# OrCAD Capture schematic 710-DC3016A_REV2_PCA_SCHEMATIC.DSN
size Custom; company: ANALOG DEVICES; note: DEMO BOARD BILL OF MATERIALS; note: 2A BUCK-BOOST POWER uMODULE REGULATOR
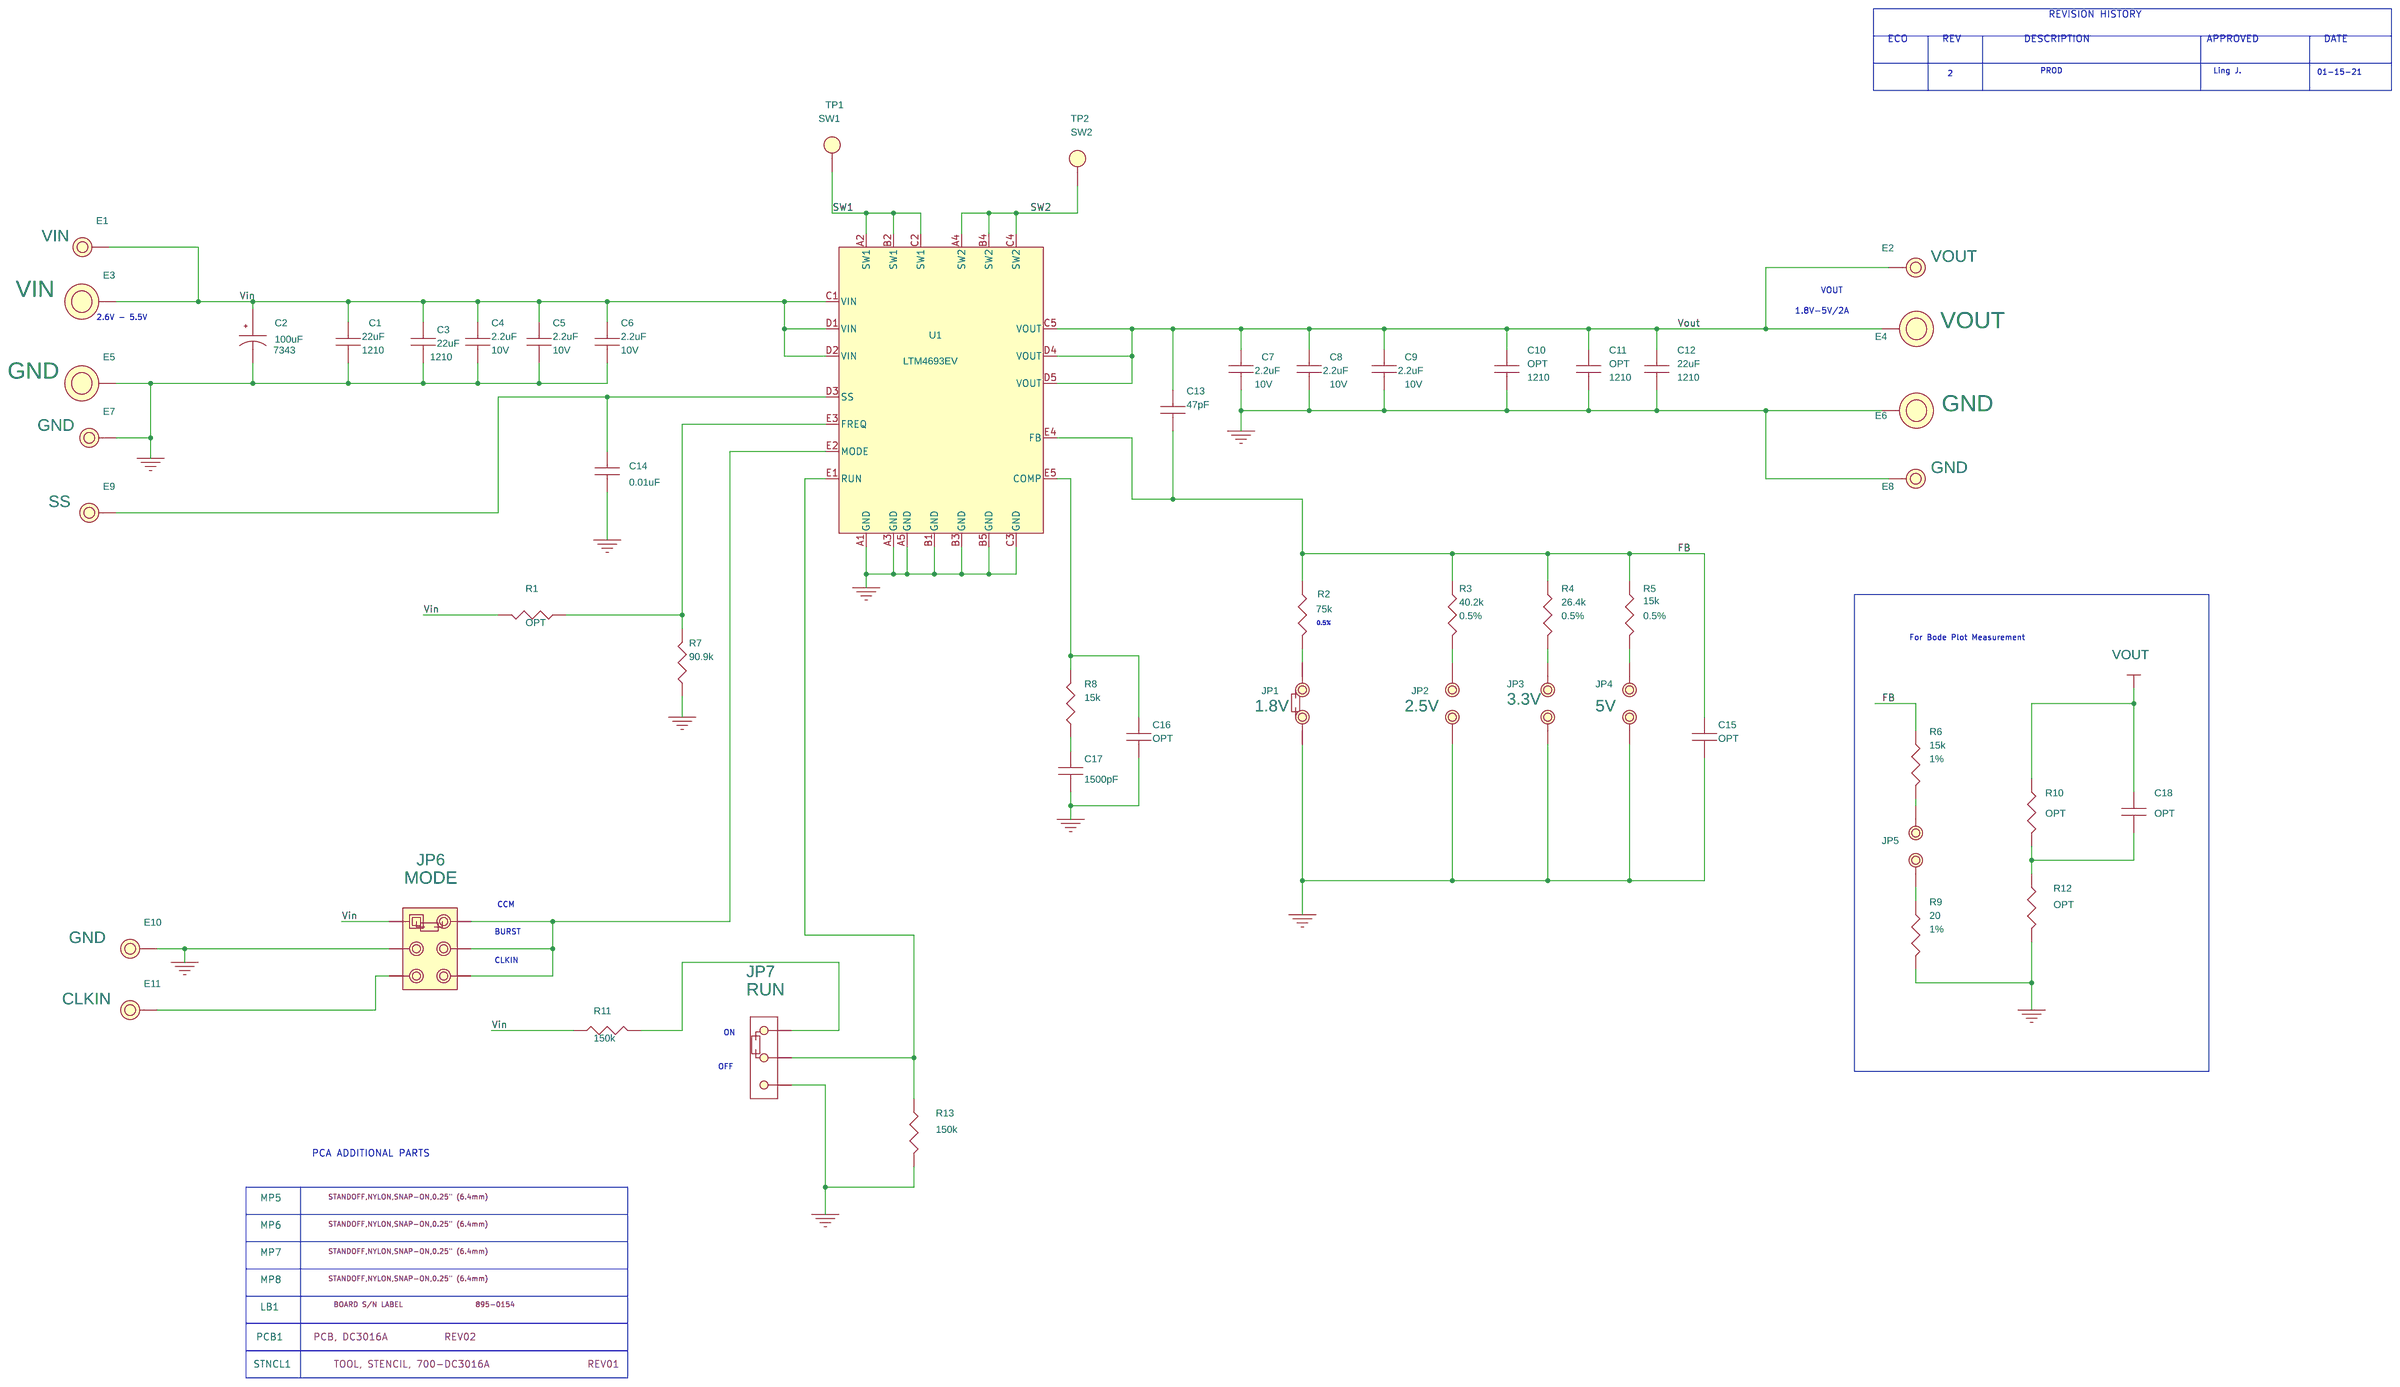
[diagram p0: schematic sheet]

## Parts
C1  22uF  [CC1210N]
C2  100uF  [CAPMP7343N]
C3  22uF  [CC1210N]
C4  2.2uF  [CC0603N]
C5  2.2uF  [CC0603N]
C6  2.2uF  [CC0603N]
C7  2.2uF  [CC0603N]
C8  2.2uF  [CC0603N]
C9  2.2uF  [CC0603N]
C10  OPT  [CC1210N]
C11  OPT  [CC1210N]
C12  22uF  [CC1210N]
C13  47pF  [CC0603N]
C14  0.01uF  [CC0603N]
C15  OPT  [CC0603N]
C16  OPT  [CC0603N]
C17  1500pF  [CC0603N]
C18  OPT  [CC0603N]
E1  TEST POINT  [MILLMAX2501]
E2  TEST POINT  [MILLMAX2501]
E3  BANANA JACK  [KEY-575-4]
E4  BANANA JACK  [KEY-575-4]
E5  BANANA JACK  [KEY-575-4]
E6  BANANA JACK  [KEY-575-4]
E7  TEST POINT  [MILLMAX2501]
E8  TEST POINT  [MILLMAX2501]
E9  TEST POINT  [MILLMAX2501]
E10  TEST POINT  [MILLMAX2501]
E11  TEST POINT  [MILLMAX2501]
JP1  HDR  [HD1X2-079]
JP2  HDR  [HD1X2-079]
JP3  HDR  [HD1X2-079]
JP4  HDR  [HD1X2-079]
JP5  HDR  [HD1X2-079]
JP6  HDR  [HD2X3-079]
JP7  HDR  [JP3X1/079]
LB1  LABEL  [895-0154_REV01]
MP5  STANDOFF  [MTG-8831]
MP6  STANDOFF  [MTG-8831]
MP7  STANDOFF  [MTG-8831]
MP8  STANDOFF  [MTG-8831]
PCB1  PCB, DC3016A
R1  OPT  [CR0603N]
R2  75k  [CR0603N]
R3  40.2k  [CR0603N]
R4  26.4k  [CR0603N]
R5  15k  [CR0603N]
R6  15k  [CR0603N]
R7  90.9k  [CR0603N]
R8  15k  [CR0603N]
R9  20  [CR0603N]
R10  OPT  [CR0603N]
R11  150k  [CR0603N]
R12  OPT  [CR0603N]
R13  150k  [CR0603N]
STNCL1  TOOL, STENCIL, 700-DC3016A
TP1  TEST PAD  [PADSTYLE1]
TP2  TEST PAD  [PADSTYLE1]
U1  LTM4693EV  [LTM4693EV]
XJP1  SHUNT  [SAMTEC-SHUNT-079]
XJP2  SHUNT  [SAMTEC-SHUNT-079]
XJP3  SHUNT  [SAMTEC-SHUNT-079]

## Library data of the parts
C1 C3 C12 = CAP: CAP.,22uF,X5R,25V,20%,1210; CLASS: DISCRETE; Dielectric Type: X5R; FPLIST: CC1210N,CC1210L,CC1210M; Inventory Qty: 6478; Manufacturer: AVX; Manufacturer PN: 12103D226MAT2A; PART_NUMBER: 150-3266; Package Size: 1210; Rated Voltage: 25V; Tolerance: 20%
C2 = CAP_P: CAP.,100uF,TANT. POSCAP,20V,20%,7343,55mOHMS, TQC, NO SUBS. ALLOWED; CLASS: DISCRETE; Dielectric Type: TANT. POSCAP; FPLIST: CAPMP7343N,CAPMP7343L,CAPMP7343M; Inventory Qty: 3536; Manufacturer: PANASONIC; Manufacturer PN: 20TQC100MYF; PART_NUMBER: 150-3320; Package Size: 7343; Rated Voltage: 20V; Tolerance: 20%
C4-C9 = CAP: CAP.,2.2uF,X7R,10V,10%,0603; CLASS: DISCRETE; Dielectric Type: X7R; FPLIST: CC0603N,CC0603L,CC0603M; Inventory Qty: 13671; Manufacturer: MURATA; Manufacturer PN: GRM188R71A225KE15D; PART_NUMBER: 150-2083; Package Size: 0603; Rated Voltage: 10V; Tolerance: 10%
C10 C11 = CAP: CAP., OPTION, 1210; CLASS: DISCRETE; FPLIST: CC1210N,CC1210L,CC1210M; PART_NUMBER: 150-3035; Package Size: 1210; Package Type: SMD
C13 = CAP: CAP.,47pF,X7R,50V,10%,0603; CLASS: DISCRETE; Dielectric Type: X7R; FPLIST: CC0603N,CC0603L,CC0603M; Inventory Qty: 8360; Manufacturer: AVX; Manufacturer PN: 06035C470KAT2A; PART_NUMBER: 150-2319; Package Size: 0603; Rated Voltage: 50V; Tolerance: 10%
C14 = CAP: CAP.,0.01uF,X7R,50V,10%,0603; CLASS: DISCRETE; Dielectric Type: X7R; FPLIST: CC0603N,CC0603L,CC0603M; Inventory Qty: 28483; Manufacturer: AVX; Manufacturer PN: 06035C103KAT2A; PART_NUMBER: 150-0002; Package Size: 0603; Rated Voltage: 50V; Tolerance: 10%
C15 = CAP: CAP., OPTION, 0603; CLASS: DISCRETE; FPLIST: CC0603N,CC0603L,CC0603M; PART_NUMBER: 150-3038; Package Size: 0603; Package Type: SMD; UserField01: OPTION
C16 C18 = CAP: CAP., OPTION, 0603; CLASS: DISCRETE; FPLIST: CC0603N,CC0603L,CC0603M; PART_NUMBER: 150-3038; Package Size: 0603; Package Type: SMD
C17 = CAP: CAP.,1500pF,X7R,50V,10%,0603; CLASS: DISCRETE; Dielectric Type: X7R; FPLIST: CC0603N,CC0603L,CC0603M; Inventory Qty: 16000; Manufacturer: AVX; Manufacturer PN: 06035C152KAT2A; PART_NUMBER: 150-0190; Package Size: 0603; Rated Voltage: 50V; Tolerance: 10%
E1 = TESTPOINT_.219_MILL-MAX_2501: TEST POINT,TURRET,0.094" MTG. HOLE,PCB 0.062" THK; CLASS: IO; Inventory Qty: 823526; Manufacturer: MILL-MAX; Manufacturer PN: 2501-2-00-80-00-00-07-0; PART_FIELD_01: VIN; PART_NUMBER: 260-0003
E2 = TESTPOINT_.219_MILL-MAX_2501: TEST POINT,TURRET,0.094" MTG. HOLE,PCB 0.062" THK; CLASS: IO; Inventory Qty: 823526; Manufacturer: MILL-MAX; Manufacturer PN: 2501-2-00-80-00-00-07-0; PART_FIELD_01: VOUT; PART_NUMBER: 260-0003
E3 = BANANA_KEYSTONE-575-4: CONN.,BANANA JACK,FEMALE,THT,NON-INSULATED,SWAGE,0.218"; CLASS: IO; Inventory Qty: 203061; Manufacturer: KEYSTONE; Manufacturer PN: 575-4; PART_FIELD_01: VIN; PART_NUMBER: 250-0428
E4 = BANANA_KEYSTONE-575-4: CONN.,BANANA JACK,FEMALE,THT,NON-INSULATED,SWAGE,0.218"; CLASS: IO; Inventory Qty: 203061; Manufacturer: KEYSTONE; Manufacturer PN: 575-4; PART_FIELD_01: VOUT; PART_NUMBER: 250-0428
E5 E6 = BANANA_KEYSTONE-575-4: CONN.,BANANA JACK,FEMALE,THT,NON-INSULATED,SWAGE,0.218"; CLASS: IO; Inventory Qty: 203061; Manufacturer: KEYSTONE; Manufacturer PN: 575-4; PART_FIELD_01: GND; PART_NUMBER: 250-0428
E7 E8 E10 = TESTPOINT_.219_MILL-MAX_2501: TEST POINT,TURRET,0.094" MTG. HOLE,PCB 0.062" THK; CLASS: IO; Inventory Qty: 823526; Manufacturer: MILL-MAX; Manufacturer PN: 2501-2-00-80-00-00-07-0; PART_FIELD_01: GND; PART_NUMBER: 260-0003
E9 = TESTPOINT_.219_MILL-MAX_2501: TEST POINT,TURRET,0.094" MTG. HOLE,PCB 0.062" THK; CLASS: IO; Inventory Qty: 823526; Manufacturer: MILL-MAX; Manufacturer PN: 2501-2-00-80-00-00-07-0; PART_FIELD_01: SS; PART_NUMBER: 260-0003
E11 = TESTPOINT_.219_MILL-MAX_2501: TEST POINT,TURRET,0.094" MTG. HOLE,PCB 0.062" THK; CLASS: IO; Inventory Qty: 823526; Manufacturer: MILL-MAX; Manufacturer PN: 2501-2-00-80-00-00-07-0; PART_FIELD_01: CLKIN; PART_NUMBER: 260-0003
JP1 = HDR1X2_ALT1_3: CONN.,HDR,MALE,1x2,2mm,VERT,ST,THT; 9th Part Field: 1.8V; CLASS: IO; Inventory Qty: 72596; Manufacturer: SULLINS CONNECTOR SOLUTIONS; Manufacturer PN: NRPN021PAEN-RC; PART_NUMBER: 250-0449
JP2 = HDR1X2_ALT1_2: CONN.,HDR,MALE,1x2,2mm,VERT,ST,THT; 9th Part Field: 2.5V; CLASS: IO; Inventory Qty: 72596; Manufacturer: SULLINS CONNECTOR SOLUTIONS; Manufacturer PN: NRPN021PAEN-RC; PART_NUMBER: 250-0449
JP3 = HDR1X2_ALT1_1: CONN.,HDR,MALE,1x2,2mm,VERT,ST,THT; 9th Part Field: 3.3V; CLASS: IO; Inventory Qty: 72596; Manufacturer: SULLINS CONNECTOR SOLUTIONS; Manufacturer PN: NRPN021PAEN-RC; PART_NUMBER: 250-0449
JP4 = HDR1X2_ALT1: CONN.,HDR,MALE,1x2,2mm,VERT,ST,THT; 9th Part Field: 5V; CLASS: IO; Inventory Qty: 72596; Manufacturer: SULLINS CONNECTOR SOLUTIONS; Manufacturer PN: NRPN021PAEN-RC; PART_NUMBER: 250-0449
JP5 = HDR1X2_ALT1_4: CONN.,HDR,MALE,1x2,2mm,VERT,ST,THT; 9th Part Field: 5V; CLASS: IO; Inventory Qty: 72596; Manufacturer: SULLINS CONNECTOR SOLUTIONS; Manufacturer PN: NRPN021PAEN-RC; PART_NUMBER: 250-0449
JP6 = HDR2X3_ALT1: CONN.,HDR,MALE,2x3,2mm,VERT,ST,THT; 9th Part Field: MODE; CLASS: IO; Inventory Qty: 28346; Manufacturer: SULLINS CONNECTOR SOLUTIONS; Manufacturer PN: NRPN032PAEN-RC; PART_NUMBER: 250-0430
JP7 = 1X3: CONN.,HDR,MALE,1x3,2mm,VERT,ST,THT,NO SUBS. ALLOWED; CLASS: IO; FPLIST: JP3X1/079,HD1X3-079; Inventory Qty: 7904; Manufacturer: SAMTEC; Manufacturer PN: TMM-103-02-L-S; PART_FIELD_01: RUN; PART_NUMBER: 250-0638
LB1 = BLANK_LABEL: LABEL SPEC, DEMO BOARD SERIAL NUMBER; Inventory Qty: 0; Manufacturer: BRADY; Manufacturer PN: THT-96-717-10; PART_FIELD_01: BOARD S/N LABEL; PART_NUMBER: 895-0154
MP5-MP8 = BLANK_MECHANICAL_PART: STANDOFF,NYLON,SNAP-ON,0.25" (6.4mm); CLASS: DISCRETE; Inventory Qty: 227624; Manufacturer: KEYSTONE; Manufacturer PN: 8831; PART_NUMBER: 763-0006
PCB1 = BLANK_PCB_PART: BOM Notes: REV02; CLASS: DISCRETE; Inventory Qty: 0; Manufacturer: MAO BANG; Manufacturer PN: 600-DC3016A; PART_NUMBER: 600-DC3016A
R1 R10 R12 = RES: RES., OPTION, 0603; CLASS: DISCRETE; FPLIST: CR0603N,CR0603L,CR0603M; PART_NUMBER: 100-2374; Package Size: 0603
R2 = RES: RES.,75k OHMS,0.5%,1/5W,0603; CLASS: DISCRETE; FPLIST: CR0603N,CR0603L,CR0603M; Inventory Qty: 20320; Manufacturer: PANASONIC; Manufacturer PN: ERJ-PB3D7502V; PART_NUMBER: TMP-7179; Package Size: 0603
R3 = RES: RES.,40.2k OHMS,0.5%,1/16W,0603,METAL THIN FILM; CLASS: DISCRETE; FPLIST: CR0603N,CR0603L,CR0603M; Inventory Qty: 9482; Manufacturer: Susumu; Manufacturer PN: RR0816P-4022-D-59C; PART_NUMBER: 100-2124; Package Size: 0603; Rated Power: 1/16W; Temperature Coefficient: +/-25ppm; Tolerance: 0.5%
R4 = RES: RES.,26.4K OHMS,0.5%,1/10W,0603,THIN FILM; CLASS: DISCRETE; FPLIST: CR0603N,CR0603L,CR0603M; Inventory Qty: 10000; Manufacturer: YAGEO; Manufacturer PN: RT0603DRE0726K4L; PART_NUMBER: 100-1564; Package Size: 0603; Rated Power: 1/10W; Temperature Coefficient: +/-50PPM; Tolerance: 0.5%
R5 = RES: RES.,15k OHMS,0.5%,1/10W,0603; CLASS: DISCRETE; FPLIST: CR0603N,CR0603L,CR0603M; Inventory Qty: 5000; Manufacturer: VISHAY; Manufacturer PN: CRCW060326K4FKEA; PART_NUMBER: TMP-5221; Package Size: 0603; Rated Power: 1/10W; Temperature Coefficient: 200ppm/C; Tolerance: 0.5%
R6 = RES: RES.,15k OHMS,1%,1/10W,0603; CLASS: DISCRETE; FPLIST: CR0603N,CR0603L,CR0603M; Inventory Qty: 31732; Manufacturer: NIC; Manufacturer PN: NRC06F1502TRF; PART_NUMBER: 100-2757; Package Size: 0603; Rated Power: 1/10W; Temperature Coefficient: 100ppm/C; Tolerance: 1%
R7 = RES: RES.,90.9k OHMS,1%,1/10W,0603,AEC-Q200; CLASS: DISCRETE; FPLIST: CR0603N,CR0603L,CR0603M; Inventory Qty: 76786; Manufacturer: VISHAY; Manufacturer PN: CRCW060390K9FKEA; PART_NUMBER: 100-2379; Package Size: 0603; Rated Power: 1/10W; Temperature Coefficient: 100ppm/C; Tolerance: 1%
R8 = RES: RES.,15k OHMS,5%,1/10W,0603; CLASS: DISCRETE; FPLIST: CR0603N,CR0603L,CR0603M; Inventory Qty: 19992; Manufacturer: YAGEO; Manufacturer PN: RC0603JR-0715KL; PART_NUMBER: 100-2607; Package Size: 0603; Rated Power: 1/10W; Temperature Coefficient: 100ppm/C; Tolerance: 5%
R9 = RES: RES.,20 OHMS,1%,1/10W,0603; CLASS: DISCRETE; FPLIST: CR0603N,CR0603L,CR0603M; Inventory Qty: 10000; Manufacturer: YAGEO; Manufacturer PN: RC0603FR-0720RL; PART_NUMBER: 100-0703; Package Size: 0603; Rated Power: 1/10W; Temperature Coefficient: 100PPM; Tolerance: 1%
R11 = RES: RES.,150k OHMS,1%,1/10W,0603; CLASS: DISCRETE; FPLIST: CR0603N,CR0603L,CR0603M; Inventory Qty: 37444; Manufacturer: PANASONIC; Manufacturer PN: ERJ3EKF1503V; PART_NUMBER: 100-2438; Package Size: 0603; Rated Power: 1/10W; Temperature Coefficient: 100ppm/C; Tolerance: 1%
R13 = RES: RES.,150k OHMS,5%,1/10W,0603,AEC-Q200; CLASS: DISCRETE; Inventory Qty: 20658; Manufacturer: PANASONIC; Manufacturer PN: ERJ3GEYJ154V; PART_NUMBER: 100-2968; Package Size: 0603; Rated Power: 1/10W; Temperature Coefficient: +-200PPM; Tolerance: 5%
STNCL1 = BLANK_STENCIL_PART: BOM Notes: REV01; CLASS: DISCRETE; Inventory Qty: 0; Manufacturer: ANALOG DEVICES; Manufacturer PN: 830-DC3016A; PART_NUMBER: 830-DC3016A
TP1 = PAD_STYLE_C: TESTPOINT, PCB COPPER FEATURE; CLASS: IO; FPLIST: PADSTYLE1,PADSTYLE2,PADSTYLE3,PADSTYLE4,PADSTYLE5,PADSTYLE6,PADSTYLE7,PADSTYLE8; Manufacturer: N/A; Manufacturer PN: N/A; PART_FIELD_01: SW1; PART_NUMBER: PCBPADS-1
TP2 = PAD_STYLE_C: TESTPOINT, PCB COPPER FEATURE; CLASS: IO; FPLIST: PADSTYLE1,PADSTYLE2,PADSTYLE3,PADSTYLE4,PADSTYLE5,PADSTYLE6,PADSTYLE7,PADSTYLE8; Manufacturer: N/A; Manufacturer PN: N/A; PART_FIELD_01: SW2; PART_NUMBER: PCBPADS-1
U1 = LTM4693: IC,BUCK BOOST POWER uMODULE,25-pin LGA; CLASS: IC; Inventory Qty: 0; Manufacturer: ANALOG DEVICES; Manufacturer PN: LTM4693EV#PBF; PART_NUMBER: LTM4693EV#PBF; Package Type: 25-pin LGA
XJP1-XJP3 = SHUNT_2MM_C: CONN.,SHUNT,FEMALE,2-POS,2mm; CLASS: MECHANICAL; Inventory Qty: 268933; Manufacturer: SAMTEC; Manufacturer PN: 2SN-BK-G; PART_NUMBER: 250-0419

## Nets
GND: C1.2 C2.2 C3.2 C4.2 C5.2 C6.2 C7.2 C8.2 C9.2 C10.2 C11.2 C12.2 C14.2 C15.2 C16.2 C17.2 E5.1 E6.1 E7.1 E8.1 E10.1 JP1.1 JP2.1 JP3.1 JP4.1 JP6.3 JP7.3 R7.1 R9.2 R12.2 R13.2 U1.A1(GND) U1.A3(GND) U1.A5(GND) U1.B1(GND) U1.B3(GND) U1.B5(GND) U1.C3(GND)
Vin: C1.1 C2.1 C3.1 C4.1 C5.1 C6.1 E1.1 E3.1 JP6.1 R1.2 R11.1 U1.C1(VIN) U1.D1(VIN) U1.D2(VIN)
FB: C13.2 C15.1 R2.1 R3.1 R4.1 R5.1 R6.1 U1.E4(FB)
SW1: TP1.1 U1.A2(SW1) U1.B2(SW1) U1.C2(SW1)
SW2: TP2.1 U1.A4(SW2) U1.B4(SW2) U1.C4(SW2)
Vout: C7.1 C8.1 C9.1 C10.1 C11.1 C12.1 C13.1 C18.1 E2.1 E4.1 R10.1 U1.C5(VOUT) U1.D4(VOUT) U1.D5(VOUT)
N9807675: C14.1 E9.1 U1.D3(SS)
N9815020: JP6.2 JP6.4 JP6.6 U1.E2(MODE)
N9815029: JP7.2 R13.1 U1.E1(RUN)
N9816069: C16.1 R8.2 U1.E5(COMP)
N9818441: C17.1 R8.1
N9820961: R1.1 R7.2 U1.E3(FREQ)
N9821222: E11.1 JP6.5
N9821540: JP7.1 R11.2
N9822722: JP4.2 R5.2
N9822834: JP1.2 R2.2
N9822886: JP2.2 R3.2
N9822890: JP3.2 R4.2
N9828508: C18.2 R10.2 R12.1
N9867076: JP5.2 R6.2
N9867096: JP5.1 R9.1

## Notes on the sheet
- REVISION HISTORY
- ECO
- REV
- DESCRIPTION
- APPROVED
- DATE
- 2
- PROD
- Ling J.
- 01-15-21
- VOUT
- 1.8V-5V/2A
- 2.6V - 5.5V
- 0.5%
- For Bode Plot Measurement
- CCM
- BURST
- CLKIN
- ON
- OFF
- PCA ADDITIONAL PARTS
